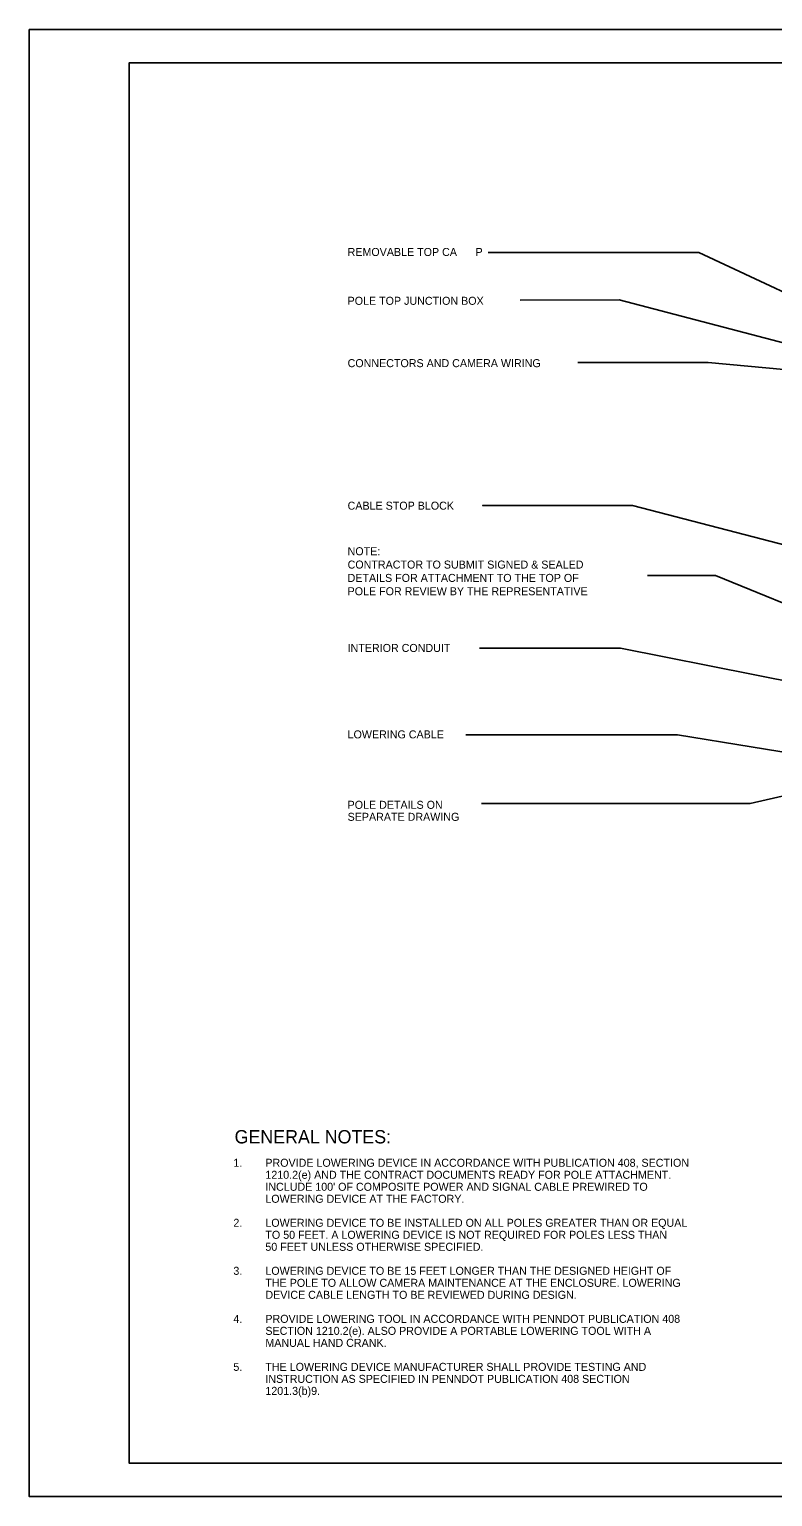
# Model space of a CAD drawing. Extents: x 1299104.6 to 1299141.4, y 239713.3 to 239735.3.
# Drawn here: x 1299104.62 to 1299115.78, y 239713.27 to 239735.27 of the extents above; entities that cross this region are included whole.
import ezdxf

# ---------------------------------------------------------------- set-up
doc = ezdxf.new("R2010")
doc.units = 0
for name, color, linetype in [('DIM TXT', 7, 'Continuous'), ('GS_plotshape_p', 7, 'Continuous'), ('Level 1', 7, 'Continuous'), ('Level 8', 7, 'Continuous')]:
    doc.layers.add(name, color=color, linetype=linetype)

msp = doc.modelspace()

# ---------------------------------------------------------------- linework, layer by layer
at = {"layer": 'GS_plotshape_p'}
msp.add_lwpolyline([(1299104.622, 239735.273), (1299138.622, 239735.273), (1299138.622, 239713.273), (1299104.622, 239713.273)], close=True, dxfattribs=at)
at = {"layer": 'Level 1'}
msp.add_lwpolyline([(1299138.122, 239713.773), (1299106.122, 239713.773), (1299106.122, 239734.773), (1299138.122, 239734.773)], close=True, dxfattribs=at)
at = {"layer": 'Level 8'}
msp.add_line((1299114.917, 239727.086), (1299113.897, 239727.086), dxfattribs=at)
for points in [[(1299117.045, 239730.819), (1299117.045, 239730.819), (1299114.668, 239731.926), (1299111.506, 239731.926)], [(1299116.186, 239730.508), (1299116.186, 239730.508), (1299113.474, 239731.216), (1299111.987, 239731.214)], [(1299117.135, 239730.061), (1299117.135, 239730.061), (1299114.808, 239730.28), (1299112.852, 239730.28)], [(1299117.543, 239727.128), (1299113.671, 239728.133), (1299111.423, 239728.133), (1299111.435, 239728.133)], [(1299116.682, 239726.363), (1299114.917, 239727.086)], [(1299117.524, 239725.194), (1299113.493, 239725.993), (1299111.375, 239725.993)], [(1299117.664, 239724.156), (1299117.664, 239724.156), (1299114.347, 239724.697), (1299111.173, 239724.697)], [(1299116.858, 239723.991), (1299115.438, 239723.667), (1299111.405, 239723.667)]]:
    msp.add_lwpolyline(points, dxfattribs=at)

# ---------------------------------------------------------------- texts
at = {"layer": 'DIM TXT'}
for s, height, p in [('REMOVABLE TOP CA', 0.12, (1299109.398, 239731.875)), ('P', 0.12, (1299111.318, 239731.875)), ('POLE TOP JUNCTION BOX', 0.12, (1299109.398, 239731.143)), ('CONNECTORS AND CAMERA WIRING', 0.12, (1299109.398, 239730.208)), ('CABLE STOP BLOCK', 0.12, (1299109.398, 239728.071)), ('NOTE:', 0.12, (1299109.398, 239727.388)), ('CONTRACTOR TO SUBMIT SIGNED & SEALED', 0.12, (1299109.398, 239727.188)), ('DETAILS FOR ATTACHMENT TO THE TOP OF', 0.12, (1299109.398, 239726.988)), ('POLE FOR REVIEW BY THE REPRESENTATIVE', 0.12, (1299109.398, 239726.788)), ('INTERIOR CONDUIT', 0.12, (1299109.398, 239725.938)), ('LOWERING CABLE', 0.12, (1299109.398, 239724.642)), ('POLE DETAILS ON', 0.12, (1299109.398, 239723.586)), ('SEPARATE DRAWING', 0.12, (1299109.398, 239723.406)), ('GENERAL NOTES:', 0.2, (1299107.702, 239718.569)), ('1.', 0.12, (1299107.684, 239718.219)), ('1210.2(e) AND THE CONTRACT DOCUMENTS READY FOR POLE ATTACHMENT. ', 0.12, (1299108.164, 239718.039)), ('PROVIDE LOWERING DEVICE IN ACCORDANCE WITH PUBLICATION 408, SECTION ', 0.12, (1299108.164, 239718.219)), ("INCLUDE 100' OF COMPOSITE POWER AND SIGNAL CABLE PREWIRED TO ", 0.12, (1299108.164, 239717.859)), ('LOWERING DEVICE AT THE FACTORY.', 0.12, (1299108.164, 239717.679)), ('2.', 0.12, (1299107.684, 239717.319)), ('LOWERING DEVICE TO BE INSTALLED ON ALL POLES GREATER THAN OR EQUAL ', 0.12, (1299108.164, 239717.319)), ('TO 50 FEET. A LOWERING DEVICE IS NOT REQUIRED FOR POLES LESS THAN ', 0.12, (1299108.164, 239717.139)), ('50 FEET UNLESS OTHERWISE SPECIFIED.', 0.12, (1299108.164, 239716.959)), ('3.', 0.12, (1299107.684, 239716.599)), ('LOWERING DEVICE TO BE 15 FEET LONGER THAN THE DESIGNED HEIGHT OF ', 0.12, (1299108.164, 239716.599)), ('THE POLE TO ALLOW CAMERA MAINTENANCE AT THE ENCLOSURE. LOWERING ', 0.12, (1299108.164, 239716.419)), ('DEVICE CABLE LENGTH TO BE REVIEWED DURING DESIGN.', 0.12, (1299108.164, 239716.239)), ('4.', 0.12, (1299107.684, 239715.879)), ('PROVIDE LOWERING TOOL IN ACCORDANCE WITH PENNDOT PUBLICATION 408 ', 0.12, (1299108.164, 239715.879)), ('SECTION 1210.2(e). ALSO PROVIDE A PORTABLE LOWERING TOOL WITH A ', 0.12, (1299108.164, 239715.699)), ('MANUAL HAND CRANK.', 0.12, (1299108.164, 239715.519)), ('5.', 0.12, (1299107.684, 239715.159)), ('THE LOWERING DEVICE MANUFACTURER SHALL PROVIDE TESTING AND ', 0.12, (1299108.164, 239715.159)), ('INSTRUCTION AS SPECIFIED IN PENNDOT PUBLICATION 408 SECTION ', 0.12, (1299108.164, 239714.979)), ('1201.3(b)9.', 0.12, (1299108.164, 239714.799))]:
    msp.add_text(s, height=height, dxfattribs=at).set_placement(p)

doc.saveas('drawing.dxf')
